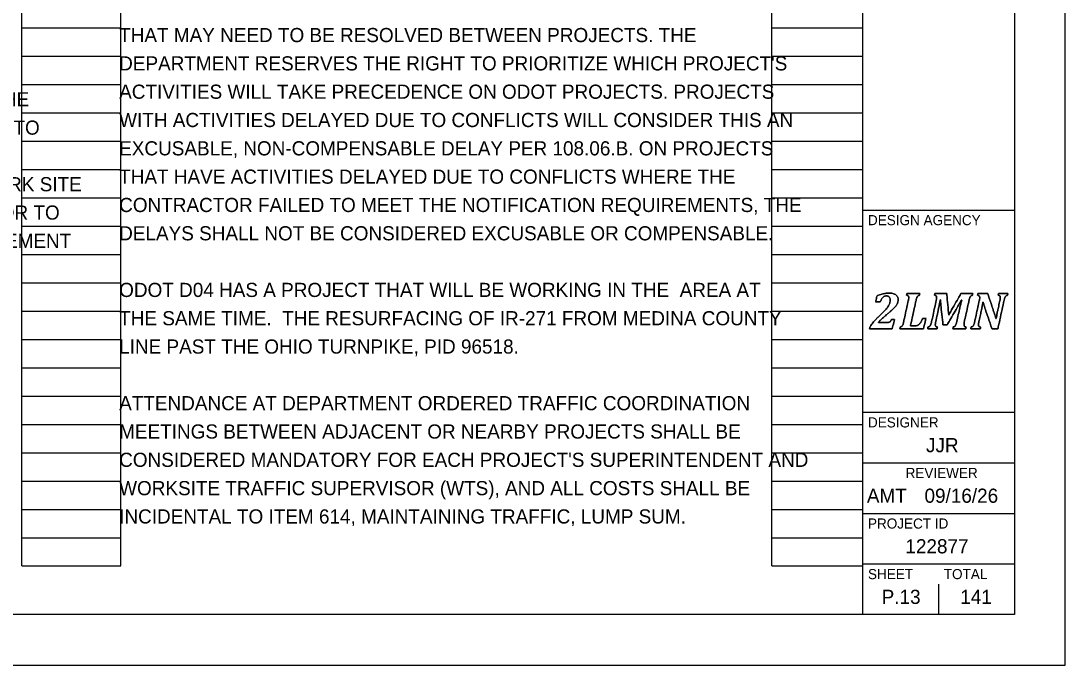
# Model space of a CAD drawing. Extents: x -26.4 to 34, y 0 to 22.
# Drawn here: x 23.67 to 34, y 0 to 6.37 of the extents above; entities that cross this region are included whole.
import ezdxf

# ---------------------------------------------------------------- set-up
doc = ezdxf.new("R2010")
doc.units = 0
for name, color, linetype in [('SH_Border', 7, 'Continuous'), ('SH_Cut_Line', 7, 'Continuous'), ('SH_Data', 7, 'Continuous'), ('SH_Text', 7, 'Continuous')]:
    doc.layers.add(name, color=color, linetype=linetype)

msp = doc.modelspace()

# ---------------------------------------------------------------- linework, layer by layer
at = {"layer": 'SH_Border'}
for p, q in [((32, 0.5), (32, 21.5)), ((32, 4.5), (33.5, 4.5)), ((32, 2.5), (33.5, 2.5)), ((32, 2), (33.5, 2)), ((32, 1.5), (33.5, 1.5)), ((32, 1), (33.5, 1))]:
    msp.add_line(p, q, dxfattribs=at)
msp.add_lwpolyline([(1.5, 21.5), (33.5, 21.5), (33.5, 0.5), (1.5, 0.5)], close=True, dxfattribs=at)
at = {"layer": 'SH_Cut_Line'}
msp.add_lwpolyline([(0, 0), (34, 0), (34, 22), (0, 22)], close=True, dxfattribs=at)
at = {"layer": 'SH_Data'}
for p, q in [((23.68, 0.98), (23.68, 21.14)), ((24.66, 0.98), (24.66, 21.14)), ((31.1, 0.98), (31.1, 21.14)), ((32, 0.98), (32, 21.14)), ((23.68, 6.3), (24.66, 6.3)), ((31.1, 6.3), (32, 6.3)), ((23.68, 6.02), (24.66, 6.02)), ((31.1, 6.02), (32, 6.02)), ((23.68, 5.74), (24.66, 5.74)), ((31.1, 5.74), (32, 5.74)), ((23.68, 5.46), (24.66, 5.46)), ((31.1, 5.46), (32, 5.46)), ((23.68, 5.18), (24.66, 5.18)), ((31.1, 5.18), (32, 5.18)), ((23.68, 4.9), (24.66, 4.9)), ((31.1, 4.9), (32, 4.9)), ((23.68, 4.62), (24.66, 4.62)), ((31.1, 4.62), (32, 4.62)), ((23.68, 4.34), (24.66, 4.34)), ((31.1, 4.34), (32, 4.34)), ((23.68, 4.06), (24.66, 4.06)), ((31.1, 4.06), (32, 4.06)), ((23.68, 3.78), (24.66, 3.78)), ((31.1, 3.78), (32, 3.78)), ((23.68, 3.5), (24.66, 3.5)), ((31.1, 3.5), (32, 3.5)), ((32.75, 3.5), (32.75, 3.5)), ((23.68, 3.22), (24.66, 3.22)), ((31.1, 3.22), (32, 3.22)), ((23.68, 2.94), (24.66, 2.94)), ((31.1, 2.94), (32, 2.94)), ((23.68, 2.66), (24.66, 2.66)), ((31.1, 2.66), (32, 2.66)), ((23.68, 2.38), (24.66, 2.38)), ((31.1, 2.38), (32, 2.38)), ((23.68, 2.1), (24.66, 2.1)), ((31.1, 2.1), (32, 2.1)), ((23.68, 1.82), (24.66, 1.82)), ((31.1, 1.82), (32, 1.82)), ((23.68, 1.54), (24.66, 1.54)), ((31.1, 1.54), (32, 1.54)), ((23.68, 1.26), (24.66, 1.26)), ((31.1, 1.26), (32, 1.26)), ((23.68, 0.98), (24.66, 0.98)), ((31.1, 0.98), (32, 0.98)), ((32.75, 0.5), (32.75, 0.8)), ((32.375, 0.675), (32.375, 0.675))]:
    msp.add_line(p, q, dxfattribs=at)
for points in [[(32.237, 3.388), (32.246, 3.388), (32.253, 3.389), (32.258, 3.39), (32.263, 3.392), (32.267, 3.394), (32.27, 3.397), (32.273, 3.401), (32.277, 3.408), (32.281, 3.417), (32.281, 3.417), (32.312, 3.417), (32.312, 3.417), (32.312, 3.417), (32.29, 3.326), (32.29, 3.326), (32.29, 3.326), (32.066, 3.326), (32.066, 3.326), (32.066, 3.326), (32.069, 3.343), (32.069, 3.343), (32.078, 3.358), (32.091, 3.375), (32.106, 3.394), (32.122, 3.412), (32.144, 3.435), (32.172, 3.462), (32.197, 3.486), (32.217, 3.506), (32.23, 3.521), (32.243, 3.537), (32.253, 3.551), (32.259, 3.566), (32.266, 3.58), (32.269, 3.595), (32.269, 3.61), (32.269, 3.622), (32.266, 3.632), (32.26, 3.64), (32.253, 3.647), (32.245, 3.65), (32.234, 3.65), (32.22, 3.65), (32.208, 3.646), (32.198, 3.636), (32.188, 3.627), (32.18, 3.613), (32.172, 3.593), (32.172, 3.593), (32.126, 3.593), (32.126, 3.593), (32.126, 3.593), (32.14, 3.654), (32.14, 3.654), (32.166, 3.663), (32.188, 3.669), (32.205, 3.673), (32.223, 3.676), (32.24, 3.678), (32.258, 3.678), (32.278, 3.678), (32.295, 3.675), (32.309, 3.669), (32.322, 3.664), (32.332, 3.656), (32.339, 3.646), (32.345, 3.637), (32.348, 3.626), (32.348, 3.613), (32.348, 3.602), (32.346, 3.591), (32.342, 3.581), (32.339, 3.571), (32.333, 3.56), (32.324, 3.549), (32.315, 3.539), (32.304, 3.526), (32.289, 3.513), (32.275, 3.499), (32.254, 3.482), (32.228, 3.46), (32.216, 3.45), (32.202, 3.438), (32.188, 3.425), (32.174, 3.412), (32.162, 3.4), (32.154, 3.391), (32.154, 3.391), (32.153, 3.388), (32.153, 3.388), (32.153, 3.388), (32.237, 3.388), (32.237, 3.388)], [(32.237, 3.388), (32.237, 3.388), (32.153, 3.388), (32.153, 3.388), (32.153, 3.388), (32.154, 3.391), (32.154, 3.391), (32.162, 3.4), (32.174, 3.412), (32.188, 3.425), (32.202, 3.438), (32.216, 3.45), (32.228, 3.46), (32.254, 3.482), (32.275, 3.499), (32.289, 3.513), (32.304, 3.526), (32.315, 3.539), (32.324, 3.549), (32.333, 3.56), (32.339, 3.571), (32.342, 3.581), (32.346, 3.591), (32.348, 3.602), (32.348, 3.613), (32.348, 3.626), (32.345, 3.637), (32.339, 3.646), (32.332, 3.656), (32.322, 3.664), (32.309, 3.669), (32.295, 3.675), (32.278, 3.678), (32.258, 3.678), (32.24, 3.678), (32.223, 3.676), (32.205, 3.673), (32.188, 3.669), (32.166, 3.663), (32.14, 3.654), (32.14, 3.654), (32.126, 3.593), (32.126, 3.593), (32.126, 3.593), (32.172, 3.593), (32.172, 3.593), (32.18, 3.613), (32.188, 3.627), (32.198, 3.636), (32.208, 3.646), (32.22, 3.65), (32.234, 3.65), (32.245, 3.65), (32.253, 3.647), (32.26, 3.64), (32.266, 3.632), (32.269, 3.622), (32.269, 3.61), (32.269, 3.595), (32.266, 3.58), (32.259, 3.566), (32.253, 3.551), (32.243, 3.537), (32.23, 3.521), (32.217, 3.506), (32.197, 3.486), (32.172, 3.462), (32.144, 3.435), (32.122, 3.412), (32.106, 3.394), (32.091, 3.375), (32.078, 3.358), (32.069, 3.343), (32.069, 3.343), (32.066, 3.326), (32.066, 3.326), (32.066, 3.326), (32.29, 3.326), (32.29, 3.326), (32.29, 3.326), (32.312, 3.417), (32.312, 3.417), (32.312, 3.417), (32.281, 3.417), (32.281, 3.417), (32.277, 3.408), (32.273, 3.401), (32.27, 3.397), (32.267, 3.394), (32.263, 3.392), (32.258, 3.39), (32.253, 3.389), (32.246, 3.388), (32.237, 3.388)], [(32.518, 3.356), (32.527, 3.356), (32.533, 3.357), (32.538, 3.358), (32.542, 3.36), (32.546, 3.362), (32.55, 3.365), (32.554, 3.368), (32.558, 3.372), (32.562, 3.377), (32.567, 3.382), (32.571, 3.388), (32.576, 3.397), (32.58, 3.405), (32.585, 3.415), (32.589, 3.427), (32.589, 3.427), (32.624, 3.427), (32.624, 3.427), (32.624, 3.427), (32.598, 3.326), (32.598, 3.326), (32.598, 3.326), (32.365, 3.326), (32.365, 3.326), (32.365, 3.326), (32.369, 3.343), (32.369, 3.343), (32.376, 3.345), (32.381, 3.348), (32.385, 3.351), (32.389, 3.355), (32.392, 3.36), (32.395, 3.366), (32.398, 3.373), (32.4, 3.382), (32.403, 3.395), (32.403, 3.395), (32.449, 3.605), (32.449, 3.605), (32.452, 3.615), (32.453, 3.625), (32.453, 3.635), (32.453, 3.642), (32.451, 3.647), (32.448, 3.651), (32.444, 3.654), (32.439, 3.656), (32.432, 3.657), (32.432, 3.657), (32.435, 3.674), (32.435, 3.674), (32.435, 3.674), (32.563, 3.674), (32.563, 3.674), (32.563, 3.674), (32.559, 3.657), (32.559, 3.657), (32.552, 3.655), (32.547, 3.652), (32.543, 3.649), (32.539, 3.645), (32.536, 3.64), (32.533, 3.634), (32.531, 3.627), (32.528, 3.618), (32.525, 3.605), (32.525, 3.605), (32.47, 3.356), (32.47, 3.356), (32.47, 3.356), (32.518, 3.356), (32.518, 3.356)], [(32.518, 3.356), (32.518, 3.356), (32.47, 3.356), (32.47, 3.356), (32.47, 3.356), (32.525, 3.605), (32.525, 3.605), (32.528, 3.618), (32.531, 3.627), (32.533, 3.634), (32.536, 3.64), (32.539, 3.645), (32.543, 3.649), (32.547, 3.652), (32.552, 3.655), (32.559, 3.657), (32.559, 3.657), (32.563, 3.674), (32.563, 3.674), (32.563, 3.674), (32.435, 3.674), (32.435, 3.674), (32.435, 3.674), (32.432, 3.657), (32.432, 3.657), (32.439, 3.656), (32.444, 3.654), (32.448, 3.651), (32.451, 3.647), (32.453, 3.642), (32.453, 3.635), (32.453, 3.625), (32.452, 3.615), (32.449, 3.605), (32.449, 3.605), (32.403, 3.395), (32.403, 3.395), (32.4, 3.382), (32.398, 3.373), (32.395, 3.366), (32.392, 3.36), (32.389, 3.355), (32.385, 3.351), (32.381, 3.348), (32.376, 3.345), (32.369, 3.343), (32.369, 3.343), (32.365, 3.326), (32.365, 3.326), (32.365, 3.326), (32.598, 3.326), (32.598, 3.326), (32.598, 3.326), (32.624, 3.427), (32.624, 3.427), (32.624, 3.427), (32.589, 3.427), (32.589, 3.427), (32.585, 3.415), (32.58, 3.405), (32.576, 3.397), (32.571, 3.388), (32.567, 3.382), (32.562, 3.377), (32.558, 3.372), (32.554, 3.368), (32.55, 3.365), (32.546, 3.362), (32.542, 3.36), (32.538, 3.358), (32.533, 3.357), (32.527, 3.356), (32.518, 3.356)], [(32.829, 3.674), (32.829, 3.674), (32.849, 3.461), (32.849, 3.461), (32.849, 3.461), (32.969, 3.674), (32.969, 3.674), (32.969, 3.674), (33.087, 3.674), (33.087, 3.674), (33.087, 3.674), (33.084, 3.657), (33.084, 3.657), (33.077, 3.655), (33.071, 3.652), (33.067, 3.649), (33.064, 3.645), (33.06, 3.64), (33.058, 3.634), (33.055, 3.627), (33.052, 3.618), (33.05, 3.605), (33.05, 3.605), (33.003, 3.395), (33.003, 3.395), (33.002, 3.39), (33.002, 3.387), (33.001, 3.384), (33.001, 3.382), (33.001, 3.379), (33, 3.376), (33, 3.373), (33, 3.369), (33, 3.365), (33, 3.358), (33.002, 3.353), (33.005, 3.349), (33.008, 3.346), (33.014, 3.344), (33.021, 3.343), (33.021, 3.343), (33.018, 3.326), (33.018, 3.326), (33.018, 3.326), (32.89, 3.326), (32.89, 3.326), (32.89, 3.326), (32.893, 3.343), (32.893, 3.343), (32.9, 3.345), (32.906, 3.348), (32.91, 3.351), (32.914, 3.355), (32.917, 3.36), (32.919, 3.366), (32.922, 3.373), (32.925, 3.382), (32.928, 3.395), (32.928, 3.395), (32.951, 3.502), (32.951, 3.502), (32.954, 3.513), (32.957, 3.529), (32.962, 3.548), (32.967, 3.568), (32.972, 3.588), (32.978, 3.609), (32.978, 3.609), (32.973, 3.609), (32.973, 3.609), (32.965, 3.594), (32.957, 3.579), (32.948, 3.563), (32.948, 3.563), (32.833, 3.364), (32.833, 3.364), (32.833, 3.364), (32.792, 3.364), (32.792, 3.364), (32.792, 3.364), (32.775, 3.518), (32.775, 3.518), (32.773, 3.537), (32.772, 3.554), (32.77, 3.569), (32.769, 3.583), (32.768, 3.597), (32.768, 3.611), (32.768, 3.611), (32.764, 3.611), (32.764, 3.611), (32.761, 3.596), (32.758, 3.578), (32.755, 3.558), (32.751, 3.538), (32.747, 3.521), (32.744, 3.507), (32.744, 3.507), (32.72, 3.395), (32.72, 3.395), (32.719, 3.39), (32.718, 3.387), (32.718, 3.384), (32.717, 3.382), (32.717, 3.379), (32.717, 3.376), (32.717, 3.373), (32.716, 3.369), (32.716, 3.365), (32.716, 3.358), (32.718, 3.353), (32.721, 3.349), (32.725, 3.346), (32.73, 3.344), (32.738, 3.343), (32.738, 3.343), (32.734, 3.326), (32.734, 3.326), (32.734, 3.326), (32.641, 3.326), (32.641, 3.326), (32.641, 3.326), (32.644, 3.343), (32.644, 3.343), (32.651, 3.345), (32.657, 3.348), (32.661, 3.351), (32.665, 3.355), (32.668, 3.36), (32.67, 3.366), (32.673, 3.373), (32.676, 3.382), (32.679, 3.395), (32.679, 3.395), (32.725, 3.605), (32.725, 3.605), (32.727, 3.615), (32.728, 3.625), (32.728, 3.635), (32.728, 3.642), (32.727, 3.647), (32.723, 3.651), (32.72, 3.654), (32.715, 3.656), (32.707, 3.657), (32.707, 3.657), (32.711, 3.674), (32.711, 3.674), (32.711, 3.674), (32.829, 3.674), (32.829, 3.674)], [(32.829, 3.674), (32.829, 3.674), (32.711, 3.674), (32.711, 3.674), (32.711, 3.674), (32.707, 3.657), (32.707, 3.657), (32.715, 3.656), (32.72, 3.654), (32.723, 3.651), (32.727, 3.647), (32.728, 3.642), (32.728, 3.635), (32.728, 3.625), (32.727, 3.615), (32.725, 3.605), (32.725, 3.605), (32.679, 3.395), (32.679, 3.395), (32.676, 3.382), (32.673, 3.373), (32.67, 3.366), (32.668, 3.36), (32.665, 3.355), (32.661, 3.351), (32.657, 3.348), (32.651, 3.345), (32.644, 3.343), (32.644, 3.343), (32.641, 3.326), (32.641, 3.326), (32.641, 3.326), (32.734, 3.326), (32.734, 3.326), (32.734, 3.326), (32.738, 3.343), (32.738, 3.343), (32.73, 3.344), (32.725, 3.346), (32.721, 3.349), (32.718, 3.353), (32.716, 3.358), (32.716, 3.365), (32.716, 3.369), (32.717, 3.373), (32.717, 3.376), (32.717, 3.379), (32.717, 3.382), (32.718, 3.384), (32.718, 3.387), (32.719, 3.39), (32.72, 3.395), (32.72, 3.395), (32.744, 3.507), (32.744, 3.507), (32.747, 3.521), (32.751, 3.538), (32.755, 3.558), (32.758, 3.578), (32.761, 3.596), (32.764, 3.611), (32.764, 3.611), (32.768, 3.611), (32.768, 3.611), (32.768, 3.597), (32.769, 3.583), (32.77, 3.569), (32.772, 3.554), (32.773, 3.537), (32.775, 3.518), (32.775, 3.518), (32.792, 3.364), (32.792, 3.364), (32.792, 3.364), (32.833, 3.364), (32.833, 3.364), (32.833, 3.364), (32.948, 3.563), (32.948, 3.563), (32.957, 3.579), (32.965, 3.594), (32.973, 3.609), (32.973, 3.609), (32.978, 3.609), (32.978, 3.609), (32.972, 3.588), (32.967, 3.568), (32.962, 3.548), (32.957, 3.529), (32.954, 3.513), (32.951, 3.502), (32.951, 3.502), (32.928, 3.395), (32.928, 3.395), (32.925, 3.382), (32.922, 3.373), (32.919, 3.366), (32.917, 3.36), (32.914, 3.355), (32.91, 3.351), (32.906, 3.348), (32.9, 3.345), (32.893, 3.343), (32.893, 3.343), (32.89, 3.326), (32.89, 3.326), (32.89, 3.326), (33.018, 3.326), (33.018, 3.326), (33.018, 3.326), (33.021, 3.343), (33.021, 3.343), (33.014, 3.344), (33.008, 3.346), (33.005, 3.349), (33.002, 3.353), (33, 3.358), (33, 3.365), (33, 3.369), (33, 3.373), (33, 3.376), (33.001, 3.379), (33.001, 3.382), (33.001, 3.384), (33.002, 3.387), (33.002, 3.39), (33.003, 3.395), (33.003, 3.395), (33.05, 3.605), (33.05, 3.605), (33.052, 3.618), (33.055, 3.627), (33.058, 3.634), (33.06, 3.64), (33.064, 3.645), (33.067, 3.649), (33.071, 3.652), (33.077, 3.655), (33.084, 3.657), (33.084, 3.657), (33.087, 3.674), (33.087, 3.674), (33.087, 3.674), (32.969, 3.674), (32.969, 3.674), (32.969, 3.674), (32.849, 3.461), (32.849, 3.461), (32.849, 3.461), (32.829, 3.674), (32.829, 3.674)], [(33.137, 3.674), (33.137, 3.674), (33.234, 3.674), (33.234, 3.674), (33.234, 3.674), (33.283, 3.53), (33.283, 3.53), (33.296, 3.49), (33.307, 3.456), (33.315, 3.426), (33.315, 3.426), (33.318, 3.426), (33.318, 3.426), (33.323, 3.455), (33.329, 3.488), (33.337, 3.523), (33.337, 3.523), (33.355, 3.605), (33.355, 3.605), (33.357, 3.615), (33.358, 3.625), (33.358, 3.635), (33.358, 3.642), (33.357, 3.647), (33.353, 3.651), (33.35, 3.654), (33.345, 3.656), (33.337, 3.657), (33.337, 3.657), (33.341, 3.674), (33.341, 3.674), (33.341, 3.674), (33.434, 3.674), (33.434, 3.674), (33.434, 3.674), (33.431, 3.657), (33.431, 3.657), (33.424, 3.655), (33.418, 3.652), (33.414, 3.649), (33.41, 3.645), (33.407, 3.64), (33.405, 3.634), (33.402, 3.627), (33.399, 3.618), (33.396, 3.605), (33.396, 3.605), (33.335, 3.326), (33.335, 3.326), (33.335, 3.326), (33.277, 3.326), (33.277, 3.326), (33.277, 3.326), (33.216, 3.504), (33.216, 3.504), (33.211, 3.518), (33.207, 3.531), (33.204, 3.543), (33.2, 3.556), (33.195, 3.571), (33.19, 3.59), (33.19, 3.59), (33.186, 3.59), (33.186, 3.59), (33.185, 3.579), (33.182, 3.563), (33.179, 3.543), (33.175, 3.523), (33.17, 3.501), (33.165, 3.478), (33.165, 3.478), (33.147, 3.395), (33.147, 3.395), (33.146, 3.39), (33.145, 3.387), (33.145, 3.384), (33.144, 3.382), (33.144, 3.379), (33.144, 3.376), (33.143, 3.373), (33.143, 3.369), (33.143, 3.365), (33.143, 3.358), (33.145, 3.353), (33.148, 3.349), (33.152, 3.346), (33.157, 3.344), (33.164, 3.343), (33.164, 3.343), (33.161, 3.326), (33.161, 3.326), (33.161, 3.326), (33.067, 3.326), (33.067, 3.326), (33.067, 3.326), (33.071, 3.343), (33.071, 3.343), (33.078, 3.345), (33.083, 3.348), (33.087, 3.351), (33.091, 3.355), (33.094, 3.36), (33.097, 3.366), (33.1, 3.373), (33.102, 3.382), (33.105, 3.395), (33.105, 3.395), (33.151, 3.605), (33.151, 3.605), (33.154, 3.615), (33.155, 3.625), (33.155, 3.635), (33.155, 3.642), (33.153, 3.647), (33.15, 3.651), (33.146, 3.654), (33.141, 3.656), (33.134, 3.657), (33.134, 3.657), (33.137, 3.674), (33.137, 3.674)], [(33.137, 3.674), (33.137, 3.674), (33.134, 3.657), (33.134, 3.657), (33.141, 3.656), (33.146, 3.654), (33.15, 3.651), (33.153, 3.647), (33.155, 3.642), (33.155, 3.635), (33.155, 3.625), (33.154, 3.615), (33.151, 3.605), (33.151, 3.605), (33.105, 3.395), (33.105, 3.395), (33.102, 3.382), (33.1, 3.373), (33.097, 3.366), (33.094, 3.36), (33.091, 3.355), (33.087, 3.351), (33.083, 3.348), (33.078, 3.345), (33.071, 3.343), (33.071, 3.343), (33.067, 3.326), (33.067, 3.326), (33.067, 3.326), (33.161, 3.326), (33.161, 3.326), (33.161, 3.326), (33.164, 3.343), (33.164, 3.343), (33.157, 3.344), (33.152, 3.346), (33.148, 3.349), (33.145, 3.353), (33.143, 3.358), (33.143, 3.365), (33.143, 3.369), (33.143, 3.373), (33.144, 3.376), (33.144, 3.379), (33.144, 3.382), (33.145, 3.384), (33.145, 3.387), (33.146, 3.39), (33.147, 3.395), (33.147, 3.395), (33.165, 3.478), (33.165, 3.478), (33.17, 3.501), (33.175, 3.523), (33.179, 3.543), (33.182, 3.563), (33.185, 3.579), (33.186, 3.59), (33.186, 3.59), (33.19, 3.59), (33.19, 3.59), (33.195, 3.571), (33.2, 3.556), (33.204, 3.543), (33.207, 3.531), (33.211, 3.518), (33.216, 3.504), (33.216, 3.504), (33.277, 3.326), (33.277, 3.326), (33.277, 3.326), (33.335, 3.326), (33.335, 3.326), (33.335, 3.326), (33.396, 3.605), (33.396, 3.605), (33.399, 3.618), (33.402, 3.627), (33.405, 3.634), (33.407, 3.64), (33.41, 3.645), (33.414, 3.649), (33.418, 3.652), (33.424, 3.655), (33.431, 3.657), (33.431, 3.657), (33.434, 3.674), (33.434, 3.674), (33.434, 3.674), (33.341, 3.674), (33.341, 3.674), (33.341, 3.674), (33.337, 3.657), (33.337, 3.657), (33.345, 3.656), (33.35, 3.654), (33.353, 3.651), (33.357, 3.647), (33.358, 3.642), (33.358, 3.635), (33.358, 3.625), (33.357, 3.615), (33.355, 3.605), (33.355, 3.605), (33.337, 3.523), (33.337, 3.523), (33.329, 3.488), (33.323, 3.455), (33.318, 3.426), (33.318, 3.426), (33.315, 3.426), (33.315, 3.426), (33.307, 3.456), (33.296, 3.49), (33.283, 3.53), (33.283, 3.53), (33.234, 3.674), (33.234, 3.674), (33.234, 3.674), (33.137, 3.674), (33.137, 3.674)]]:
    msp.add_open_spline(points, degree=3, dxfattribs=at)

# ---------------------------------------------------------------- texts
for s, height, p in [('DESIGN AGENCY', 0.1, (32.05, 4.35)), ('DESIGNER', 0.1, (32.05, 2.35)), ('JJR', 0.14, (32.624, 2.105)), ('REVIEWER', 0.1, (32.422, 1.85)), ('AMT', 0.14, (32.039, 1.605)), ('09/16/26', 0.14, (32.609, 1.605)), ('PROJECT ID', 0.1, (32.05, 1.35)), ('122877', 0.14, (32.42, 1.105)), ('SHEET', 0.1, (32.05, 0.85)), ('TOTAL', 0.1, (32.8, 0.85)), ('P.13', 0.14, (32.185, 0.605)), ('141', 0.14, (32.963, 0.605))]:
    msp.add_text(s, height=height, dxfattribs=at).set_placement(p)
at = {"layer": 'SH_Text'}
for s, p in [('THAT MAY NEED TO BE RESOLVED BETWEEN PROJECTS. THE ', (24.643, 6.16)), ("DEPARTMENT RESERVES THE RIGHT TO PRIORITIZE WHICH PROJECT'S ", (24.643, 5.88)), ('ACTIVITIES WILL TAKE PRECEDENCE ON ODOT PROJECTS. PROJECTS ', (24.643, 5.6)), ('DURING NIGHTTIME PERIODS SHALL BE ACCOMPLISHED SO THAT THE ', (17.252, 5.525)), ('LIGHTS DO NOT CAUSE GLARE TO THE DRIVERS ON THE ROADWAY. TO ', (17.252, 5.245)), ('WITH ACTIVITIES DELAYED DUE TO CONFLICTS WILL CONSIDER THIS AN ', (24.643, 5.32)), ('EXCUSABLE, NON-COMPENSABLE DELAY PER 108.06.B. ON PROJECTS ', (24.643, 5.04)), ('THAT HAVE ACTIVITIES DELAYED DUE TO CONFLICTS WHERE THE ', (24.643, 4.76)), ('CONTRACTOR AND THE ENGINEER SHALL DRIVE THROUGH THE WORK SITE ', (17.252, 4.685)), ('EACH NIGHT WHEN THE LIGHTING IS IN PLACE AND OPERATIVE PRIOR TO ', (17.252, 4.405)), ('CONTRACTOR FAILED TO MEET THE NOTIFICATION REQUIREMENTS, THE ', (24.643, 4.48)), ('DELAYS SHALL NOT BE CONSIDERED EXCUSABLE OR COMPENSABLE.', (24.643, 4.2)), ('COMMENCING ANY WORK. IF GLARE IS DETECTED, THE LIGHT PLACEMENT ', (17.252, 4.125)), ('ODOT D04 HAS A PROJECT THAT WILL BE WORKING IN THE  AREA AT', (24.643, 3.64)), ('THE SAME TIME.  THE RESURFACING OF IR-271 FROM MEDINA COUNTY ', (24.643, 3.36)), ('LINE PAST THE OHIO TURNPIKE, PID 96518.', (24.643, 3.08)), ('ATTENDANCE AT DEPARTMENT ORDERED TRAFFIC COORDINATION ', (24.643, 2.52)), ('MEETINGS BETWEEN ADJACENT OR NEARBY PROJECTS SHALL BE ', (24.643, 2.24)), ("CONSIDERED MANDATORY FOR EACH PROJECT'S SUPERINTENDENT AND ", (24.643, 1.96)), ('WORKSITE TRAFFIC SUPERVISOR (WTS), AND ALL COSTS SHALL BE ', (24.643, 1.68)), ('INCIDENTAL TO ITEM 614, MAINTAINING TRAFFIC, LUMP SUM.', (24.643, 1.4))]:
    msp.add_text(s, height=0.14, dxfattribs=at).set_placement(p)

doc.saveas('drawing.dxf')
